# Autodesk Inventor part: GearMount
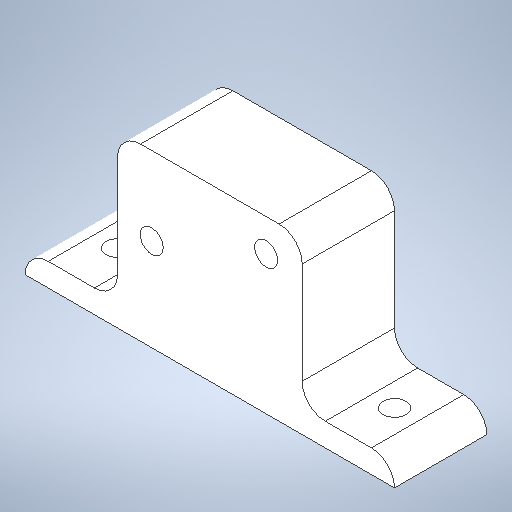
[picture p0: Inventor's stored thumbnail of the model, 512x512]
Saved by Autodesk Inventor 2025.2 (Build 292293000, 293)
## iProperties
Created: 2025-09
Part Number: GearMount
Material: Generic
Document SubType Name: Modeling
Designer: tyler
Density: 1 g/cm^3
Appearance: Default
Author: tyler
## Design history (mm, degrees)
sketch "Sketch1"
  geometry: L1 (-25.4, -6.35)-(25.4, -6.35); L2 (25.4, -6.35)-(25.4, 6.35); L3 (25.4, 6.35)-(-25.4, 6.35); L4 (-25.4, 6.35)-(-25.4, -6.35); L5 (-25.4, -6.35)-(25.4, 6.35); L6 (25.4, -6.35)-(-25.4, 6.35); L7 (25.4, -6.35)-(12.7, 6.35); L8 (25.4, -6.35)-(43.361, -6.35); L9 (-25.4, -6.35)-(-12.7, 6.35); C1 r 1.588 at (19.05, 0); C2 r 1.587 at (-19.05, 0); 1 further point
  constraints: 18 end point, 4 midpoint, 2 centre point, 2 horizontal, 2 parallel, 2 point on line, 1 equal length, 1 perpendicular
  dimensions: "d0" = 50.8 distance of L3.end L2.end; "d1" = 12.7 distance of L2.end L1.end; "d2" = 135 deg angle of L8 L7; "d3" = 3.175 diameter of C1; "d4" = 3.175 diameter of C2
extrude "Extrusion1" new body sketch "Sketch1" distance "d5" = 3.175; taper "d6" = 0 deg
sketch "Sketch2"
  geometry: L1 (-25.4, 6.35)-(-25.4, -6.35) reference; L2 (-25.4, 6.35)-(-12.7, -6.35); L3 (-25.4, -6.35)-(25.4, -6.35) reference; L4 (-25.4, 6.35)-(-7.439, 6.35); L5 (-12.7, -6.35)-(-12.7, 6.35); L6 (25.4, -6.35)-(25.4, 6.35) reference; L7 (25.4, 6.35)-(12.7, -6.35); L8 (25.4, 6.35)-(43.361, 6.35); L9 (12.7, -6.35)-(12.7, 6.35); L10 (25.4, 6.35)-(-25.4, 6.35) reference; L11 (-12.7, -6.35)-(12.7, -6.35); 1 further point
  constraints: 14 end point, 3 point on line, 2 equal length, 2 horizontal, 1 collinear, 1 perpendicular
  dimensions: "d7" = 45 deg angle of L2 L4; "d8" = 135 deg angle of L7 L8
extrude "Extrusion2" join sketch "Sketch2" distance "d9" = 20.32; taper "d10" = 0 deg
sketch "Sketch3"
  geometry: L1 (0, 0)-(50.8, 0) reference; L2 (12.7, 3.175)-(12.7, 23.495) reference; L3 (17.399, 12.7)-(33.147, 19.05); C1 r 1.588 at (17.399, 12.7); C2 r 1.587 at (33.147, 19.05); C3 r 6.413 at (17.399, 12.7); C4 r 6.413 at (33.147, 19.05); 1 further point
  constraints: 4 centre point, 2 coincident, 2 end point
  dimensions: "d11" = 3.175 diameter of C1; "d12" = 3.175 diameter of C2; "d13" = 12.7 distance from line of L3.start L1; "d14" = 19.05 distance from line of L3.end L1; "d15" = 4.699 distance from line of L2 L3.start; "d16" = 15.748 horizontal distance of L3.start L3.end; "d17" = 6.35 vertical distance of L3.start L3.end (derived); "d24" = 12.827 diameter of C3; "d25" = 12.827 diameter of C4
extrude "Extrusion3" cut sketch "Sketch3" distance "d18" = 25.4; taper "d19" = 0 deg
fillet "Fillet1" dims "d20" = 3.175
fillet "Fillet2" dims "d21" = 3.175
fillet "Fillet3" dims "d22" = 3.175
fillet "Fillet4" dims "d23" = 3.175
body "Solid1"
